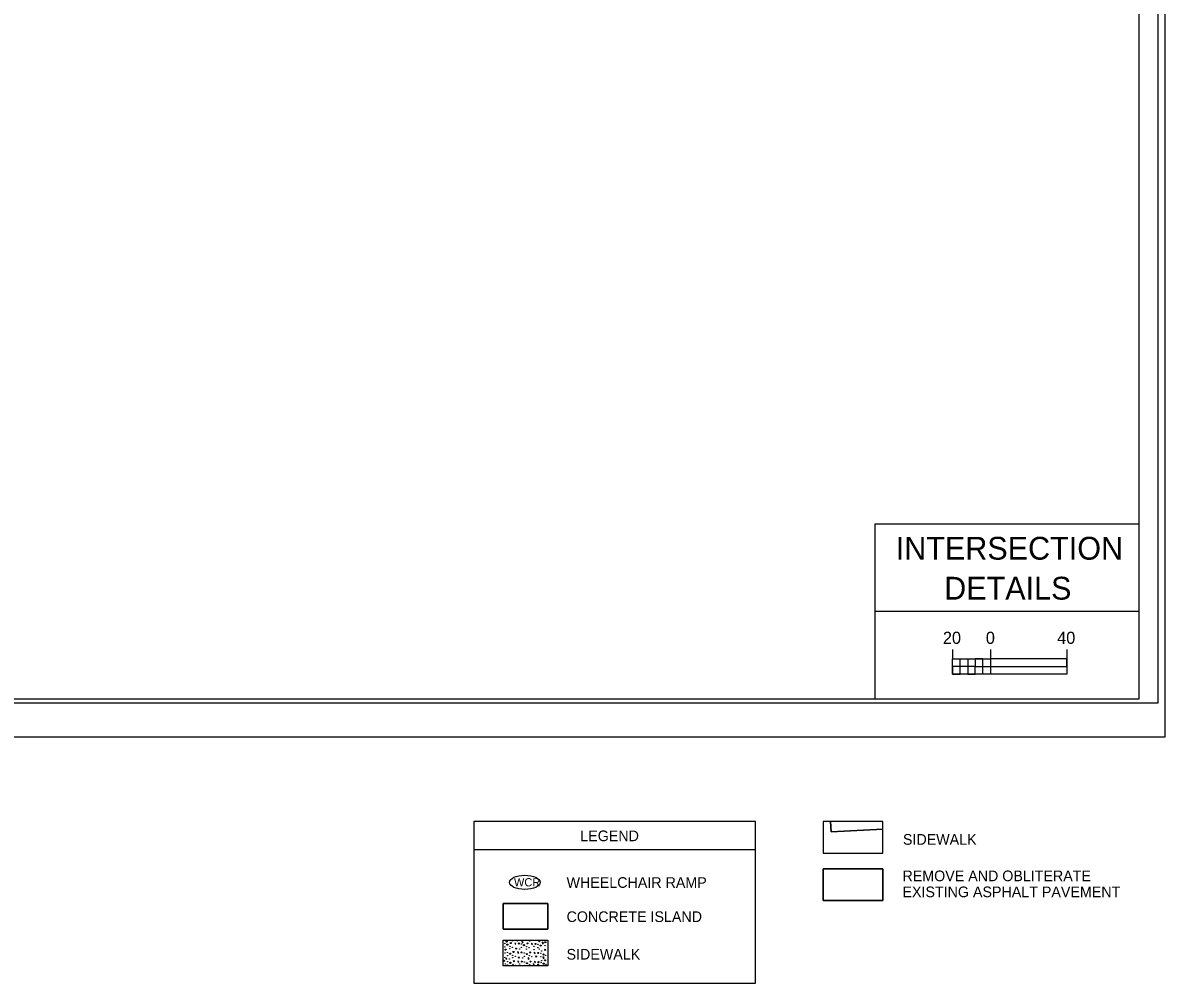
# Model space of a CAD drawing. Extents: x 2431000 to 2534000, y 645879 to 714000.
# Drawn here: x 2465774 to 2466524, y 661112 to 661743 of the extents above; entities that cross this region are included whole.
import ezdxf

# ---------------------------------------------------------------- set-up
doc = ezdxf.new("R2010")
doc.units = 0
for name, color, linetype in [('Default', 7, 'Continuous'), ('Level 25', 7, 'Continuous'), ('Old_Level_1', 7, 'Continuous'), ('Old_Level_40', 7, 'Continuous'), ('Prop DSN Text', 7, 'Continuous'), ('Prop Rem of Exist Asph Pvmt', 7, 'Continuous'), ('Prop Shade Light', 7, 'Continuous'), ('Prop WCC CELL', 7, 'Continuous'), ('Sheet Plan CELL', 7, 'Continuous'), ('Sheet Plot Border Inside CELL', 7, 'Continuous'), ('Sheet Plot Border Outside CELL', 7, 'Continuous'), ('Sheet Typical CELL', 7, 'Continuous')]:
    doc.layers.add(name, color=color, linetype=linetype)

msp = doc.modelspace()

# ---------------------------------------------------------------- linework, layer by layer
at = {"layer": 'Level 25'}
msp.add_lwpolyline([(2466089.55, 661164.11), (2466089.55, 661147.27), (2466118.74, 661147.27), (2466118.74, 661164.11), (2466089.55, 661164.11)], dxfattribs=at)
for points in [[(2466097.89, 661137.65), (2466097.14, 661138.25), (2466097.32, 661137.22)], [(2466102.54, 661138.53), (2466101.79, 661139.13), (2466101.97, 661138.1)], [(2466108.82, 661137.36), (2466108.07, 661137.96), (2466108.25, 661136.93)], [(2466115.97, 661137.93), (2466115.22, 661138.53), (2466115.4, 661137.5)], [(2466091.99, 661127.71), (2466091.25, 661128.31), (2466091.42, 661127.28)], [(2466099.69, 661131.76), (2466098.94, 661132.36), (2466099.12, 661131.33)], [(2466106.59, 661127.87), (2466105.84, 661128.47), (2466106.01, 661127.44)], [(2466110.62, 661131.47), (2466109.88, 661132.07), (2466110.05, 661131.04)], [(2466116.41, 661128.43), (2466115.66, 661129.03), (2466115.84, 661128)], [(2466099.85, 661125.74), (2466099.1, 661126.34), (2466099.28, 661125.31)], [(2466109.95, 661123.94), (2466109.21, 661124.54), (2466109.38, 661123.51)], [(2466110.78, 661125.46), (2466110.04, 661126.06), (2466110.21, 661125.03)]]:
    msp.add_lwpolyline(points, close=True, dxfattribs=at)
for centre, radius in [((2466090.57, 661137.75), 0.131), ((2466090.57, 661135.58), 0.131), ((2466091.78, 661139.06), 0.356), ((2466092.25, 661136.97), 0.356), ((2466093.98, 661135.96), 0.131), ((2466094.5, 661138.09), 0.356), ((2466095.73, 661139.5), 0.131), ((2466098.7, 661139.34), 0.131), ((2466099.75, 661137.77), 0.356), ((2466101.5, 661137.46), 0.131), ((2466101.5, 661135.3), 0.131), ((2466103.18, 661136.69), 0.356), ((2466104.91, 661135.67), 0.131), ((2466105.44, 661137.8), 0.356), ((2466106.96, 661139.34), 0.131), ((2466109.76, 661135.98), 0.131), ((2466110.69, 661137.48), 0.356), ((2466112.44, 661137.18), 0.131), ((2466113.25, 661139.06), 0.131), ((2466114.12, 661136.4), 0.356), ((2466117.19, 661138.61), 0.356), ((2466117.06, 661136.42), 0.131), ((2466090.68, 661131.49), 0.131), ((2466090.68, 661128.56), 0.131), ((2466091.09, 661133.72), 0.356), ((2466092.37, 661131.86), 0.131), ((2466092.38, 661129.69), 0.131), ((2466094.05, 661131.08), 0.356), ((2466093.88, 661134.32), 0.131), ((2466095.6, 661135.28), 0.131), ((2466095.68, 661128.43), 0.131), ((2466095.78, 661130.07), 0.131), ((2466096.31, 661132.19), 0.356), ((2466097.41, 661129.38), 0.131), ((2466097.98, 661134.42), 0.356), ((2466099.78, 661128.53), 0.356), ((2466100.42, 661134.15), 0.131), ((2466101.56, 661131.88), 0.356), ((2466102.22, 661128.26), 0.131), ((2466103.31, 661131.57), 0.131), ((2466103.31, 661129.4), 0.131), ((2466104.99, 661130.79), 0.356), ((2466104.87, 661134.05), 0.131), ((2466106.53, 661134.99), 0.131), ((2466106.72, 661129.78), 0.131), ((2466107.24, 661131.91), 0.356), ((2466108.34, 661129.09), 0.131), ((2466109.76, 661133.73), 0.131), ((2466111.14, 661129.23), 0.356), ((2466112.49, 661131.59), 0.356), ((2466112.44, 661135.01), 0.131), ((2466113.13, 661134.17), 0.131), ((2466114.24, 661131.28), 0.131), ((2466114.24, 661129.11), 0.131), ((2466114.81, 661132.77), 0.131), ((2466115.92, 661130.51), 0.356), ((2466117.15, 661133.6), 0.356), ((2466117.46, 661129.96), 0.131), ((2466090.21, 661126.43), 0.356), ((2466090.96, 661124.35), 0.131), ((2466092.53, 661125.84), 0.131), ((2466092.54, 661123.68), 0.131), ((2466093.61, 661127.56), 0.131), ((2466094.21, 661125.07), 0.356), ((2466095.94, 661124.06), 0.131), ((2466096.47, 661126.18), 0.356), ((2466097.57, 661123.37), 0.131), ((2466100.27, 661124.22), 0.131), ((2466101.72, 661125.87), 0.356), ((2466103.47, 661125.56), 0.131), ((2466103.47, 661123.39), 0.131), ((2466105.15, 661124.78), 0.356), ((2466106.88, 661123.77), 0.131), ((2466107.4, 661125.89), 0.356), ((2466112.54, 661123.9), 0.356), ((2466112.65, 661125.58), 0.356), ((2466114.4, 661125.27), 0.131), ((2466114.81, 661126.44), 0.131), ((2466116.08, 661124.49), 0.356), ((2466117.03, 661126.71), 0.356), ((2466117.62, 661124.07), 0.131)]:
    msp.add_circle(centre, radius, dxfattribs=at)
at = {"layer": 'Old_Level_1'}
msp.add_lwpolyline([(2466299.68, 661217.81), (2466299.68, 661197.04), (2466338.84, 661197.04), (2466338.84, 661217.81), (2466299.68, 661217.81)], dxfattribs=at)
for points in [[(2466299.68, 661186.73), (2466338.84, 661186.73), (2466338.84, 661165.96), (2466299.68, 661165.96)], [(2466089.55, 661164.11), (2466118.74, 661164.11), (2466118.74, 661147.27), (2466089.55, 661147.27)], [(2466089.55, 661139.89), (2466118.74, 661139.89), (2466118.74, 661123.05), (2466089.55, 661123.05)]]:
    msp.add_lwpolyline(points, close=True, dxfattribs=at)
at = {"layer": 'Old_Level_40'}
for p, q in [((2466384.56, 661330.93), (2466384.56, 661324.68)), ((2466409.56, 661330.93), (2466409.56, 661324.68))]:
    msp.add_line(p, q, dxfattribs=at)
msp.add_lwpolyline([(2466459.56, 661330.93), (2466459.56, 661314.68), (2466384.56, 661314.68), (2466384.56, 661324.68), (2466409.56, 661324.68)], dxfattribs=at)
for points in [[(2466394.56, 661319.68), (2466389.56, 661319.68), (2466389.56, 661324.68), (2466394.56, 661324.68)], [(2466404.56, 661324.68), (2466399.56, 661324.68), (2466399.56, 661319.68), (2466404.56, 661319.68)], [(2466459.56, 661324.68), (2466409.56, 661324.68), (2466409.56, 661319.68), (2466459.56, 661319.68)], [(2466389.56, 661319.68), (2466384.56, 661319.68), (2466384.56, 661314.68), (2466389.56, 661314.68)], [(2466399.56, 661319.68), (2466394.56, 661319.68), (2466394.56, 661314.68), (2466399.56, 661314.68)], [(2466409.56, 661314.68), (2466404.56, 661314.68), (2466404.56, 661319.68), (2466409.56, 661319.68)]]:
    msp.add_lwpolyline(points, close=True, dxfattribs=at)
at = {"layer": 'Prop Rem of Exist Asph Pvmt'}
msp.add_lwpolyline([(2466299.68, 661186.73), (2466299.68, 661165.96), (2466338.84, 661165.96), (2466338.84, 661186.73), (2466299.68, 661186.73)], dxfattribs=at)
at = {"layer": 'Prop Shade Light'}
for p, q in [((2466304.82, 661211.21), (2466304.48, 661217.81)), ((2466338.84, 661217.81), (2466304.48, 661217.81)), ((2466304.48, 661217.81), (2466304.82, 661211.21)), ((2466338.84, 661212.91), (2466304.82, 661211.21)), ((2466304.82, 661211.21), (2466338.84, 661212.91)), ((2466338.84, 661212.91), (2466338.84, 661217.81))]:
    msp.add_line(p, q, dxfattribs=at)
msp.add_lwpolyline([(2466304.48, 661217.81), (2466299.68, 661217.81), (2466299.68, 661197.04), (2466338.84, 661197.04), (2466338.84, 661212.91)], dxfattribs=at)
at = {"layer": 'Prop WCC CELL'}
msp.add_ellipse((2466103.73, 661177.94), major_axis=(10.09, 0), ratio=0.462467, dxfattribs=at)
at = {"layer": 'Sheet Plan CELL'}
msp.add_line((2466070.13, 661199.49), (2466255.18, 661199.49), dxfattribs=at)
for points in [[(2466507.2, 661413.32), (2466333.64, 661413.27), (2466333.65, 661355.84)], [(2466507.22, 661355.89), (2466333.65, 661355.84), (2466333.67, 661298.4)]]:
    msp.add_lwpolyline(points, dxfattribs=at)
msp.add_lwpolyline([(2466255.18, 661217.81), (2466070.13, 661217.81), (2466070.13, 661111.71), (2466255.18, 661111.71)], close=True, dxfattribs=at)
at = {"layer": 'Sheet Plot Border Inside CELL'}
msp.add_lwpolyline([(2464853.73, 661295.96), (2466519.73, 661295.96), (2466519.73, 662350.96), (2464853.73, 662350.96)], close=True, dxfattribs=at)
at = {"layer": 'Sheet Plot Border Outside CELL'}
msp.add_lwpolyline([(2464840.73, 661273.46), (2466524.23, 661273.46), (2466524.23, 662373.46), (2464840.73, 662373.46)], close=True, dxfattribs=at)
at = {"layer": 'Sheet Typical CELL'}
msp.add_lwpolyline([(2466507.23, 662348.46), (2465007.23, 662348.46), (2465007.23, 661298.46), (2466507.23, 661298.46)], close=True, dxfattribs=at)

# ---------------------------------------------------------------- texts
at = {"layer": 'Default'}
for s, p in [('LEGEND', (2466140.16, 661204.98)), ('REMOVE AND OBLITERATE', (2466351.73, 661178.68)), ('EXISTING ASPHALT PAVEMENT', (2466351.73, 661168.18))]:
    msp.add_text(s, height=7, dxfattribs=at).set_placement(p)
for s, rotation, p in [('SIDEWALK', 0.01753, (2466352.04, 661202.64)), ('WHEELCHAIR RAMP', 359.99994, (2466131.14, 661174.33)), ('CONCRETE ISLAND', 359.99994, (2466131.14, 661151.88)), ('SIDEWALK', 359.99994, (2466131.14, 661127.19))]:
    msp.add_text(s, height=7, rotation=rotation, dxfattribs=at).set_placement(p)
at = {"layer": 'Old_Level_40'}
for s, p in [('20', (2466378.28, 661334.6)), ('0', (2466406.48, 661334.6)), ('40', (2466453.32, 661334.6))]:
    msp.add_text(s, height=8, dxfattribs=at).set_placement(p)
at = {"layer": 'Prop DSN Text'}
for s, p in [('INTERSECTION', (2466347.28, 661389.91)), ('DETAILS', (2466379.1, 661363.66))]:
    msp.add_text(s, height=15, rotation=360, dxfattribs=at).set_placement(p)
at = {"layer": 'Prop WCC CELL'}
msp.add_text('WCR', height=5.4, dxfattribs=at).set_placement((2466096.6, 661175.28))

doc.saveas('drawing.dxf')
